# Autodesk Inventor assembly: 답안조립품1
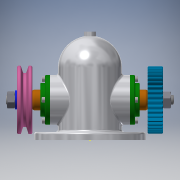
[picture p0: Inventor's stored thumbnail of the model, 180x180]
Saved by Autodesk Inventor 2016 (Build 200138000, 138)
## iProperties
Created: 2019-11
Part Number: 답안조립품1
Material: 일반
Document SubType Name: Assembly
Designer: 605-04
Author: 605-04
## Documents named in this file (14)
- C:\Users\605-04\Desktop\491104V1001\답안조립품1.iam
- C:\Users\605-04\Desktop\491104V1001\본체.ipt
- C:\Users\605-04\Desktop\491104V1001\V-벨트풀리.ipt
- V-벨트풀리.ipt
- C:\Users\605-04\Desktop\491104V1001\너트 M12x1.25.ipt
- C:\Users\605-04\Desktop\491104V1001\베어링 6203.ipt
- C:\Users\605-04\Desktop\491104V1001\볼트 M4.ipt
- C:\Users\605-04\Desktop\491104V1001\부시.ipt
- C:\Users\605-04\Desktop\491104V1001\스퍼기어.ipt
- C:\Users\605-04\Desktop\491104V1001\오일 실 26 38 8.ipt
- C:\Users\605-04\Desktop\491104V1001\와셔 12x24.ipt
- C:\Users\605-04\Desktop\491104V1001\축.ipt
- C:\Users\605-04\Desktop\491104V1001\커버.ipt
- C:\Users\605-04\Desktop\491104V1001\키 5x5x12.ipt
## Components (1 placed, 1 different names)
1. V-벨트풀리:1
## Named parameters: d3_d2 = 0
